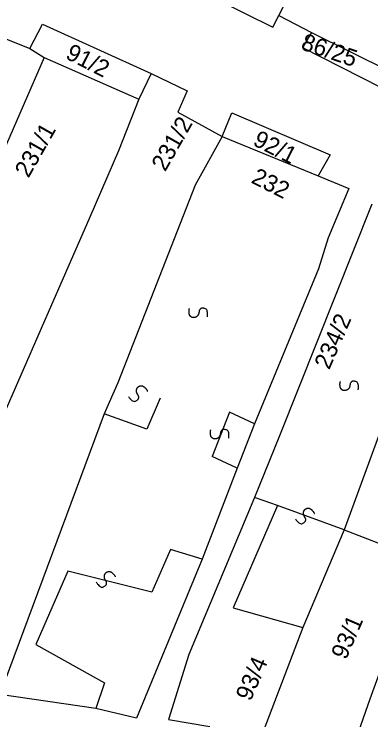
# Model space of a CAD drawing. Extents: x -581999 to -572728, y -1219553 to -1212032.
# Drawn here: x -578073.6 to -578031.4, y -1215897.1 to -1215813.7 of the extents above; entities that cross this region are included whole.
import ezdxf

# ---------------------------------------------------------------- set-up
doc = ezdxf.new("R2010")
doc.units = 0
for name, color, linetype in [('Vrstva 1', 7, 'Continuous'), ('Vrstva 2', 7, 'Continuous'), ('Vrstva 4', 7, 'Continuous'), ('Vrstva 6', 7, 'Continuous')]:
    doc.layers.add(name, color=color, linetype=linetype)

msp = doc.modelspace()

# ---------------------------------------------------------------- linework, layer by layer
at = {"layer": 'Vrstva 1'}
for p, q in [((-578042.464, -1215871.76), (-578045.189, -1215870.804)), ((-578042.464, -1215871.76), (-578047.71, -1215883.839)), ((-578047.71, -1215883.839), (-578039.49, -1215886.181))]:
    msp.add_line(p, q, dxfattribs=at)
for points in [[(-578042.299, -1215813.881), (-578038.24, -1215805.978)], [(-578049.709, -1215811.937), (-578043.003, -1215815.29), (-578042.299, -1215813.881)], [(-578042.299, -1215813.881), (-578038.448, -1215815.919)], [(-578071.73, -1215817.81), (-578070.244, -1215814.929), (-578057.395, -1215820.732)], [(-578075.152, -1215816.405), (-578071.73, -1215817.81)], [(-578038.448, -1215815.919), (-578039.503, -1215817.679), (-578030.313, -1215822.375), (-578029.17, -1215820.526)], [(-578038.448, -1215815.919), (-578029.17, -1215820.526)], [(-578071.73, -1215817.81), (-578070.039, -1215818.857)], [(-578070.039, -1215818.857), (-578074.879, -1215830.017), (-578082.113, -1215845.93)], [(-578070.039, -1215818.857), (-578058.847, -1215823.793)], [(-578057.395, -1215820.732), (-578058.847, -1215823.793)], [(-578057.395, -1215820.732), (-578053.143, -1215822.79), (-578054.259, -1215825.3)], [(-578058.847, -1215823.793), (-578061.237, -1215829.898)], [(-578054.259, -1215825.3), (-578048.992, -1215828.198)], [(-578048.992, -1215828.198), (-578047.876, -1215825.409), (-578036.266, -1215830.337), (-578037.659, -1215832.845)], [(-578048.992, -1215828.198), (-578052.194, -1215833.929)], [(-578048.992, -1215828.198), (-578037.659, -1215832.845)], [(-578061.237, -1215829.898), (-578064.657, -1215837.707), (-578070.393, -1215850.865)], [(-578037.659, -1215832.845), (-578034.055, -1215834.342)], [(-578052.194, -1215833.929), (-578061.347, -1215857.267)], [(-578034.055, -1215834.342), (-578036.485, -1215840.148)], [(-578031.335, -1215836.195), (-578042.221, -1215863.528)], [(-578036.485, -1215840.148), (-578037.632, -1215843.81), (-578045.181, -1215862.111)], [(-578024.088, -1215845.983), (-578034.581, -1215874.641)], [(-578070.393, -1215850.865), (-578075.208, -1215861.874), (-578087.892, -1215893.03)], [(-578061.347, -1215857.267), (-578062.948, -1215860.927)], [(-578062.948, -1215860.927), (-578075.305, -1215894.097)], [(-578045.181, -1215862.111), (-578047.24, -1215867.372)], [(-578042.221, -1215863.528), (-578045.189, -1215870.804), (-578052.957, -1215889.362)], [(-578047.24, -1215867.372), (-578051.359, -1215878.123)], [(-578034.581, -1215874.641), (-578039.49, -1215886.181)], [(-578034.581, -1215874.641), (-578025.612, -1215878.113)], [(-578051.359, -1215878.123), (-578059.135, -1215896.877), (-578063.912, -1215895.722)], [(-578026.852, -1215881.655), (-578031.546, -1215894.646)], [(-578039.49, -1215886.181), (-578044.397, -1215899.072)], [(-578052.957, -1215889.362), (-578055.35, -1215897.057), (-578050.467, -1215897.863)], [(-578063.912, -1215895.722), (-578075.305, -1215894.097)], [(-578031.546, -1215894.646), (-578033.708, -1215900.688)]]:
    msp.add_lwpolyline(points, dxfattribs=at)
at = {"layer": 'Vrstva 4'}
msp.add_line((-578034.581, -1215874.641), (-578042.464, -1215871.76), dxfattribs=at)
for points in [[(-578056.321, -1215859.089), (-578057.907, -1215862.751), (-578062.948, -1215860.927)], [(-578045.181, -1215862.111), (-578048.137, -1215860.73), (-578050.196, -1215865.992)], [(-578047.24, -1215867.372), (-578050.196, -1215865.992)], [(-578051.359, -1215878.123), (-578055.101, -1215876.982), (-578057.297, -1215881.985), (-578067.248, -1215879.521), (-578071.03, -1215888.184), (-578062.904, -1215892.719), (-578063.912, -1215895.722)]]:
    msp.add_lwpolyline(points, dxfattribs=at)
at = {"layer": 'Vrstva 6'}
for points in [[(-578050.755, -1215849.466), (-578050.66, -1215848.615), (-578051.39, -1215848.403), (-578051.707, -1215848.657), (-578051.752, -1215849.073), (-578051.903, -1215849.38), (-578052.152, -1215849.547), (-578052.379, -1215849.591), (-578052.642, -1215849.535), (-578052.897, -1215849.271), (-578052.937, -1215848.661), (-578052.867, -1215848.492)], [(-578032.927, -1215858.09), (-578032.832, -1215857.239), (-578033.562, -1215857.027), (-578033.879, -1215857.281), (-578033.924, -1215857.697), (-578034.075, -1215858.004), (-578034.324, -1215858.171), (-578034.551, -1215858.215), (-578034.814, -1215858.159), (-578035.069, -1215857.895), (-578035.109, -1215857.285), (-578035.039, -1215857.116)], [(-578060.083, -1215858.89), (-578059.603, -1215859.597), (-578058.909, -1215859.286), (-578058.832, -1215858.886), (-578059.068, -1215858.541), (-578059.153, -1215858.209), (-578059.071, -1215857.919), (-578058.927, -1215857.739), (-578058.691, -1215857.611), (-578058.326, -1215857.647), (-578057.899, -1215858.086), (-578057.844, -1215858.259)], [(-578048.227, -1215863.796), (-578048.132, -1215862.945), (-578048.862, -1215862.733), (-578049.179, -1215862.987), (-578049.224, -1215863.403), (-578049.375, -1215863.71), (-578049.624, -1215863.877), (-578049.851, -1215863.921), (-578050.114, -1215863.865), (-578050.369, -1215863.601), (-578050.409, -1215862.991), (-578050.339, -1215862.822)], [(-578040.358, -1215873.348), (-578039.878, -1215874.055), (-578039.184, -1215873.744), (-578039.107, -1215873.344), (-578039.343, -1215872.999), (-578039.428, -1215872.667), (-578039.346, -1215872.377), (-578039.202, -1215872.197), (-578038.966, -1215872.069), (-578038.601, -1215872.105), (-578038.174, -1215872.544), (-578038.119, -1215872.717)], [(-578063.876, -1215880.83), (-578063.396, -1215881.537), (-578062.702, -1215881.226), (-578062.625, -1215880.826), (-578062.861, -1215880.481), (-578062.946, -1215880.149), (-578062.864, -1215879.859), (-578062.72, -1215879.679), (-578062.484, -1215879.551), (-578062.119, -1215879.587), (-578061.692, -1215880.026), (-578061.637, -1215880.199)]]:
    msp.add_open_spline(points, degree=2, dxfattribs=at)

# ---------------------------------------------------------------- texts
at = {"layer": 'Vrstva 2'}
for s, rotation, p in [('86/25', 341.38126, (-578039.819, -1215817.865)), ('91/2', 333.12485, (-578067.624, -1215818.924)), ('231/2', 60.40476, (-578055.736, -1215832.422)), ('231/1', 60.40476, (-578071.886, -1215833.171)), ('92/1', 333.12485, (-578045.497, -1215829.151)), ('232', 333.12485, (-578045.697, -1215833.59)), ('234/2', 66.44012, (-578036.369, -1215855.824)), ('93/1', 66.44012, (-578034.388, -1215890.077)), ('93/4', 66.44012, (-578045.657, -1215894.973))]:
    msp.add_text(s, height=2, rotation=rotation, dxfattribs=at).set_placement(p)

doc.saveas('drawing.dxf')
